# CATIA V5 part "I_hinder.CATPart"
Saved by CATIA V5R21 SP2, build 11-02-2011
Part number: I_hinder
Bounding box of the stored display mesh (mm): x -100 to 100, y -30 to 30, z 0 to 150
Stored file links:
  \\ariel.ad.iei.liu.se\LAB_DELMIA\A1_LAB_INTRO_2011\LAB_INTRO_DATA_2011\I_hinder.CATPart
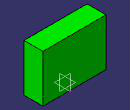
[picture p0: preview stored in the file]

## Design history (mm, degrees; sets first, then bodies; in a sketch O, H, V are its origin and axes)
Body1 (main body)
  Sketch1 on xy-plane, origin (0, 0, 0), H (1, 0, 0), V (0, 1, 0)
    line L1 (-100, -30) -> (100, -30)
    line L2 (100, -30) -> (100, 30)
    line L3 (100, 30) -> (-100, 30)
    line L4 (-100, 30) -> (-100, -30)
    horizontal: L1 H, L3 H
    vertical: L2 V, L4 V
  Pad1: profile Sketch1, direction (0, 0, 1), length 150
